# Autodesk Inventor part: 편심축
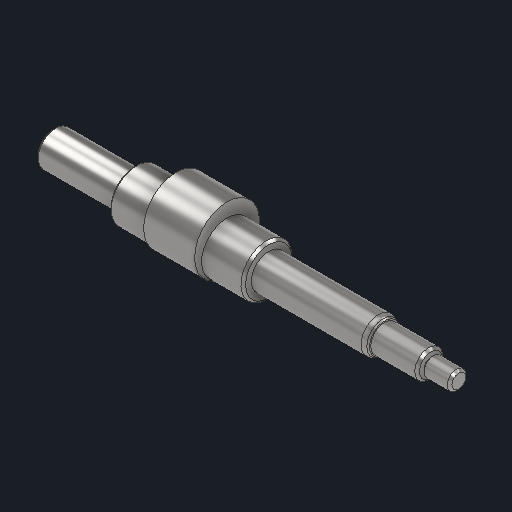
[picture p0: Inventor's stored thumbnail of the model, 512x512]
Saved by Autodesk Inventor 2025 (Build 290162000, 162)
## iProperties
Created: 2025-08
Part Number: 편심축
Material: 강철, 연강
Document SubType Name: Modeling
Designer: infra11
Density: 7.86 g/cm^3
Appearance: 기본값
Author: jhkim
Sending System: Autodesk Inventor 2026
Preprocessor: ST-DEVELOPER v20.1
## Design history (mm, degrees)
feature "솔리드1"
node "솔리드2"
